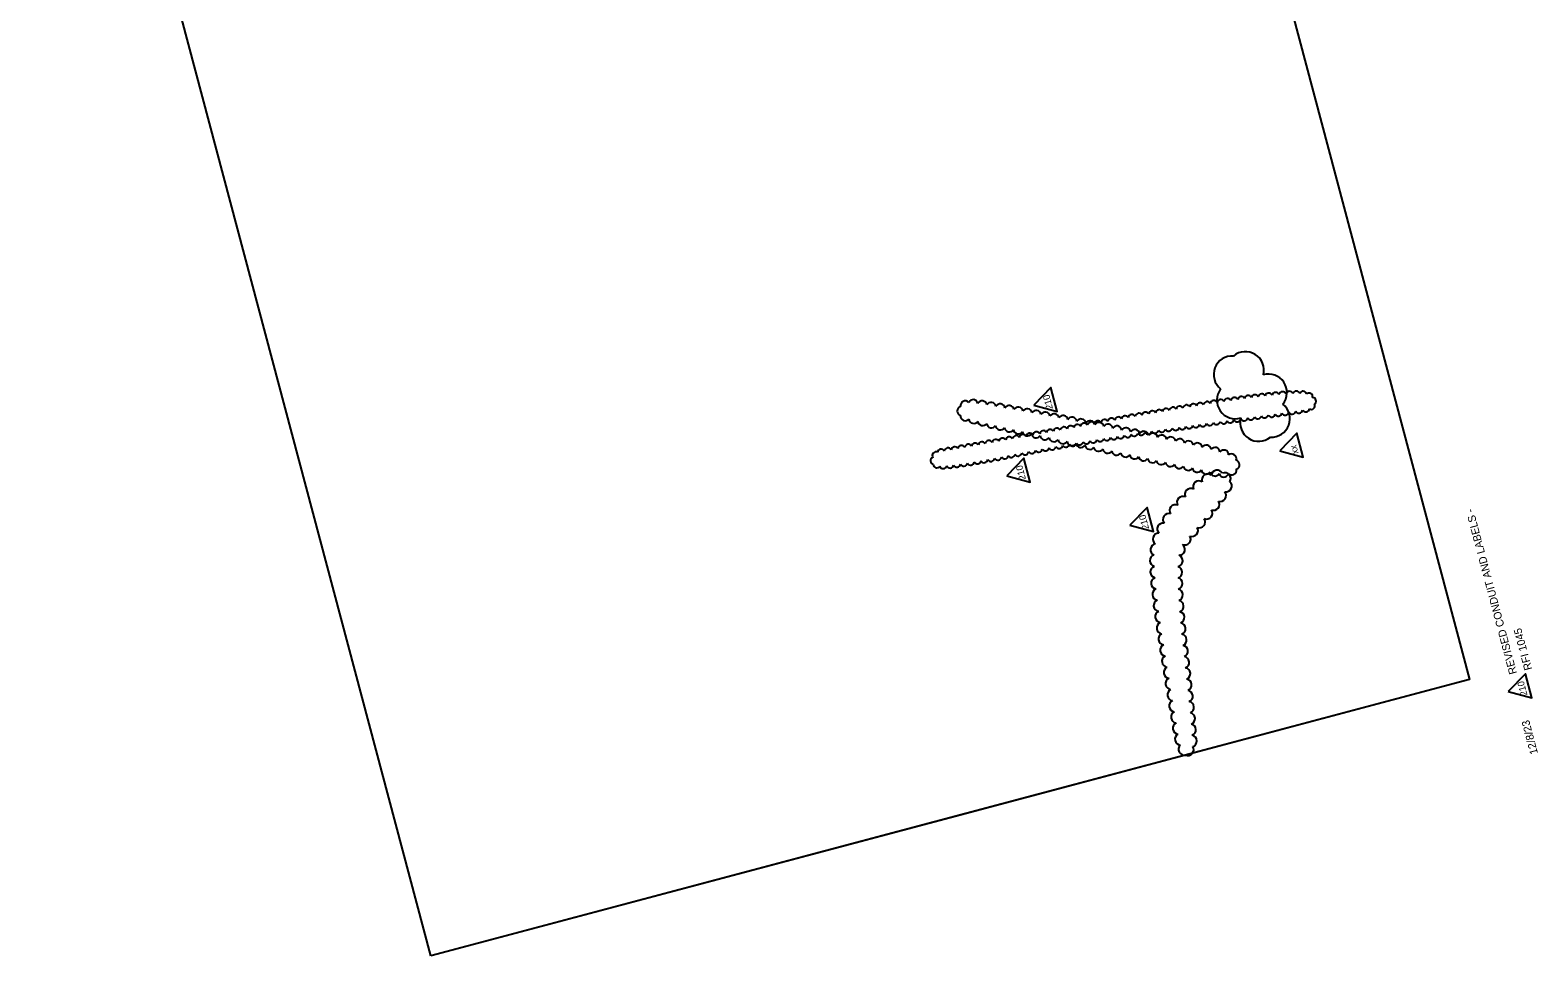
# Model space of a CAD drawing. Extents: x 930425 to 930963, y 629099 to 629760.
# Drawn here: x 930425 to 930963, y 629099 to 629430 of the extents above; entities that cross this region are included whole.
import ezdxf

# ---------------------------------------------------------------- set-up
doc = ezdxf.new("R2010")
doc.units = 0
for name, color, linetype in [('ActivePointCell_dp', 7, 'Continuous'), ('Cloud_dp', 7, 'Continuous'), ('MatchLines_dp', 7, 'Continuous'), ('TextMinor', 7, 'Continuous')]:
    doc.layers.add(name, color=color, linetype=linetype)

msp = doc.modelspace()

# ---------------------------------------------------------------- linework, layer by layer
at = {"layer": 'ActivePointCell_dp'}
msp.add_lwpolyline([(930567.78, 629098.98), (930424.61, 629637.39), (930795.69, 629736.06), (930938.85, 629197.65)], close=True, dxfattribs=at)
at = {"layer": 'Cloud_dp'}
for points in [[(930783.18, 629295.64), (930791.56, 629293.4), (930789.29, 629301.93)], [(930871.03, 629279.3), (930879.41, 629277.07), (930877.14, 629285.6)], [(930773.53, 629270.44), (930781.91, 629268.21), (930779.64, 629276.74)], [(930817.52, 629252.77), (930825.89, 629250.54), (930823.63, 629259.07)], [(930952.7, 629193.34), (930961.08, 629191.11), (930958.81, 629199.64)]]:
    msp.add_lwpolyline(points, close=True, dxfattribs=at)
for centre, radius, start, end in [((930854.07, 629306.59), 6.61, 86.2568, 231.2568), ((930858.79, 629308.17), 6.6, 345.4968, 130.4968), ((930867, 629300.17), 6.61, 321.0699, 106.0699), ((930855.17, 629297.42), 6.6, 142.5249, 287.5249), ((930758.69, 629295.46), 1.71, 43.9678, 188.9678), ((930761.48, 629295.93), 1.71, 10.359, 155.359), ((930764.7, 629295.48), 1.71, 8.6105, 153.6105), ((930767.92, 629294.96), 1.71, 7.9713, 152.9713), ((930771.14, 629294.41), 1.71, 7.609, 152.609), ((930840.18, 629294.83), 1.3, 26.844, 171.844), ((930842.62, 629295.23), 1.3, 26.7008, 171.7008), ((930845.07, 629295.62), 1.3, 26.5436, 171.5436), ((930847.51, 629296.01), 1.3, 26.37, 171.37), ((930849.95, 629296.38), 1.3, 26.177, 171.177), ((930852.4, 629296.75), 1.3, 25.9606, 170.9606), ((930854.85, 629297.11), 1.3, 25.7158, 170.7158), ((930857.3, 629297.46), 1.3, 25.4357, 170.4357), ((930859.74, 629297.79), 1.3, 25.1109, 170.1109), ((930862.2, 629298.11), 1.3, 24.7281, 169.7281), ((930864.65, 629298.41), 1.3, 24.2679, 169.2679), ((930867.1, 629298.69), 1.3, 23.7, 168.7), ((930868.07, 629290.83), 6.6, 266.857, 51.857), ((930869.56, 629298.94), 1.3, 22.9748, 167.9748), ((930872.02, 629299.16), 1.3, 22.0033, 167.0033), ((930874.48, 629299.32), 1.3, 20.605, 165.605), ((930876.94, 629299.41), 1.3, 18.3351, 163.3351), ((930879.38, 629299.34), 1.3, 13.5993, 158.5993), ((930881.5, 629298.68), 1.3, 346.9177, 131.9177), ((930882.27, 629295.45), 1.3, 240.1543, 25.1543), ((930882.73, 629297.09), 1.3, 303.2569, 88.2569), ((930757.5, 629293.55), 1.71, 106.9021, 251.9021), ((930758.68, 629291.82), 1.71, 176.383, 321.383), ((930761.73, 629290.83), 1.71, 182.8883, 327.8883), ((930774.36, 629293.84), 1.71, 7.3675, 152.3675), ((930777.57, 629293.26), 1.71, 7.1917, 152.1917), ((930780.79, 629292.67), 1.71, 7.0563, 152.0563), ((930784, 629292.08), 1.71, 6.9479, 151.9479), ((930787.21, 629291.48), 1.71, 6.8585, 151.8585), ((930790.42, 629290.87), 1.71, 6.7831, 151.7831), ((930793.63, 629290.26), 1.71, 6.7185, 151.7185), ((930796.84, 629289.65), 1.71, 6.6622, 151.6622), ((930800.05, 629289.03), 1.71, 6.6127, 151.6127), ((930808.51, 629289.25), 1.3, 27.8353, 172.8353), ((930810.94, 629289.7), 1.3, 27.8368, 172.8368), ((930813.38, 629290.14), 1.3, 27.8381, 172.8381), ((930815.81, 629290.59), 1.3, 27.8076, 172.8076), ((930818.24, 629291.03), 1.3, 27.737, 172.737), ((930820.68, 629291.46), 1.3, 27.6621, 172.6621), ((930823.11, 629291.9), 1.3, 27.5827, 172.5827), ((930825.55, 629292.33), 1.3, 27.4981, 172.4981), ((930827.99, 629292.76), 1.3, 27.4079, 172.4079), ((930830.43, 629293.18), 1.3, 27.3114, 172.3114), ((930832.86, 629293.6), 1.3, 27.2077, 172.2077), ((930835.3, 629294.02), 1.3, 27.096, 172.096), ((930837.74, 629294.43), 1.3, 26.9752, 171.9752), ((930855.85, 629290.99), 1.3, 205.3755, 350.3755), ((930863.52, 629289.34), 6.6, 164.3635, 309.3635), ((930858.3, 629291.33), 1.3, 205.399, 350.399), ((930860.75, 629291.67), 1.3, 205.4266, 350.4266), ((930863.2, 629292.01), 1.3, 205.4594, 350.4594), ((930865.65, 629292.36), 1.3, 205.4993, 350.4993), ((930868.1, 629292.7), 1.3, 205.5495, 350.5495), ((930870.55, 629293.05), 1.3, 205.6152, 350.6152), ((930873, 629293.4), 1.3, 205.7067, 350.7067), ((930875.45, 629293.76), 1.3, 205.847, 350.847), ((930877.9, 629294.12), 1.3, 206.1063, 351.1063), ((930880.34, 629294.51), 1.3, 206.992, 351.992), ((930764.89, 629290.04), 1.71, 183.793, 328.793), ((930768.06, 629289.28), 1.71, 184.2516, 329.2516), ((930771.24, 629288.54), 1.71, 184.5419, 329.5419), ((930774.43, 629287.81), 1.71, 184.747, 329.747), ((930777.62, 629287.09), 1.71, 184.9019, 329.9019), ((930779.29, 629283.93), 1.3, 27.8062, 172.8062), ((930780.81, 629286.38), 1.71, 185.0243, 330.0243), ((930781.73, 629284.38), 1.3, 27.8101, 172.8101), ((930784, 629285.68), 1.71, 185.1241, 330.1241), ((930784.16, 629284.82), 1.3, 27.8135, 172.8135), ((930786.59, 629285.26), 1.3, 27.8166, 172.8166), ((930789.03, 629285.7), 1.3, 27.8195, 172.8195), ((930791.46, 629286.15), 1.3, 27.822, 172.822), ((930793.9, 629286.59), 1.3, 27.8244, 172.8244), ((930796.33, 629287.04), 1.3, 27.8266, 172.8266), ((930798.77, 629287.48), 1.3, 27.8286, 172.8286), ((930801.2, 629287.92), 1.3, 27.8304, 172.8304), ((930803.26, 629288.41), 1.71, 6.5687, 151.5687), ((930803.64, 629288.37), 1.3, 27.8322, 172.8322), ((930806.07, 629288.81), 1.3, 27.8338, 172.8338), ((930806.47, 629287.79), 1.71, 6.5211, 151.5211), ((930809.68, 629287.17), 1.71, 6.4341, 151.4341), ((930812.88, 629286.54), 1.71, 6.3325, 151.3325), ((930816.09, 629285.9), 1.71, 6.2185, 151.2185), ((930816.64, 629285.44), 1.3, 206.1721, 351.1721), ((930819.29, 629285.26), 1.71, 6.0895, 151.0895), ((930819.09, 629285.82), 1.3, 206.0661, 351.0661), ((930821.54, 629286.18), 1.3, 205.9637, 350.9637), ((930822.49, 629284.61), 1.71, 5.942, 150.942), ((930823.99, 629286.54), 1.3, 205.8644, 350.8644), ((930825.69, 629283.95), 1.71, 5.771, 150.771), ((930826.44, 629286.9), 1.3, 205.7683, 350.7683), ((930828.88, 629287.26), 1.3, 205.6752, 350.6752), ((930831.34, 629287.61), 1.3, 205.5848, 350.5848), ((930833.79, 629287.95), 1.3, 205.4971, 350.4971), ((930836.24, 629288.29), 1.3, 205.4119, 350.4119), ((930838.69, 629288.63), 1.3, 205.3292, 350.3292), ((930841.14, 629288.97), 1.3, 205.283, 350.283), ((930843.59, 629289.31), 1.3, 205.294, 350.294), ((930846.05, 629289.64), 1.3, 205.3069, 350.3069), ((930848.5, 629289.98), 1.3, 205.3212, 350.3212), ((930850.95, 629290.31), 1.3, 205.3371, 350.3371), ((930853.4, 629290.65), 1.3, 205.3551, 350.3551), ((930750.07, 629278.65), 1.3, 27.7031, 172.7031), ((930752.5, 629279.09), 1.3, 27.5808, 172.5808), ((930754.94, 629279.52), 1.3, 27.6691, 172.6691), ((930757.37, 629279.96), 1.3, 27.7102, 172.7102), ((930759.81, 629280.4), 1.3, 27.7353, 172.7353), ((930762.25, 629280.84), 1.3, 27.7527, 172.7527), ((930764.68, 629281.28), 1.3, 27.7657, 172.7657), ((930767.12, 629281.72), 1.3, 27.7758, 172.7758), ((930769.55, 629282.16), 1.3, 27.7841, 172.7841), ((930771.99, 629282.61), 1.3, 27.7909, 172.7909), ((930774.42, 629283.05), 1.3, 27.7968, 172.7968), ((930776.86, 629283.49), 1.3, 27.8018, 172.8018), ((930784.9, 629280.13), 1.3, 207.9824, 352.9824), ((930787.19, 629284.98), 1.71, 185.2075, 330.2075), ((930787.34, 629280.58), 1.3, 207.8053, 352.8053), ((930789.77, 629281.02), 1.3, 207.6363, 352.6363), ((930790.38, 629284.29), 1.71, 185.2786, 330.2786), ((930792.21, 629281.45), 1.3, 207.4747, 352.4747), ((930793.58, 629283.6), 1.71, 185.3401, 330.3401), ((930794.65, 629281.88), 1.3, 207.3199, 352.3199), ((930796.77, 629282.91), 1.71, 185.394, 330.394), ((930797.09, 629282.3), 1.3, 207.1716, 352.1716), ((930799.97, 629282.23), 1.71, 185.4418, 330.4418), ((930799.53, 629282.71), 1.3, 207.0293, 352.0293), ((930801.97, 629283.12), 1.3, 206.8926, 351.8926), ((930803.16, 629281.55), 1.71, 185.4845, 330.4845), ((930804.42, 629283.52), 1.3, 206.7612, 351.7612), ((930806.36, 629280.87), 1.71, 185.5055, 330.5055), ((930806.86, 629283.91), 1.3, 206.6346, 351.6346), ((930809.56, 629280.19), 1.71, 185.5055, 330.5055), ((930809.3, 629284.3), 1.3, 206.5127, 351.5127), ((930811.75, 629284.69), 1.3, 206.3951, 351.3951), ((930814.19, 629285.07), 1.3, 206.2817, 351.2817), ((930828.89, 629283.28), 1.71, 5.5694, 150.5694), ((930832.09, 629282.6), 1.71, 5.327, 150.327), ((930835.28, 629281.9), 1.71, 5.0277, 150.0277), ((930838.46, 629281.18), 1.71, 4.6453, 149.6453), ((930841.64, 629280.44), 1.71, 4.1321, 149.1321), ((930844.81, 629279.67), 1.71, 3.3909, 148.3909), ((930847.96, 629278.84), 1.71, 2.1775, 147.1775), ((930747.55, 629275.81), 1.3, 111.2802, 256.2802), ((930748.21, 629277.65), 1.3, 64.1224, 209.1224), ((930748.54, 629274.56), 1.3, 180.3209, 325.3209), ((930755.71, 629274.79), 1.3, 205.3611, 350.3611), ((930758.15, 629275.15), 1.3, 206.2991, 351.2991), ((930760.59, 629275.54), 1.3, 206.9591, 351.9591), ((930763.03, 629275.96), 1.3, 207.4561, 352.4561), ((930765.46, 629276.4), 1.3, 207.8477, 352.8477), ((930767.89, 629276.85), 1.3, 208.1666, 353.1666), ((930770.32, 629277.31), 1.3, 208.4328, 353.4328), ((930772.75, 629277.78), 1.3, 208.6594, 353.6594), ((930775.17, 629278.27), 1.3, 208.763, 353.763), ((930777.6, 629278.75), 1.3, 208.5684, 353.5684), ((930780.03, 629279.22), 1.3, 208.3631, 353.3631), ((930782.47, 629279.68), 1.3, 208.1681, 353.1681), ((930812.75, 629279.51), 1.71, 185.5055, 330.5055), ((930815.95, 629278.83), 1.71, 185.5055, 330.5055), ((930819.15, 629278.15), 1.71, 185.5055, 330.5055), ((930822.35, 629277.47), 1.71, 185.5055, 330.5055), ((930825.54, 629276.79), 1.71, 185.5055, 330.5055), ((930828.74, 629276.11), 1.71, 185.5055, 330.5055), ((930831.94, 629275.43), 1.71, 185.5055, 330.5055), ((930835.13, 629274.75), 1.71, 185.5055, 330.5055), ((930851.07, 629277.91), 1.71, 359.5656, 144.5656), ((930853.83, 629276.54), 1.71, 342.5668, 127.5668), ((930854.98, 629274.38), 1.71, 288.8016, 73.8016), ((930750.82, 629274.28), 1.3, 200.9023, 345.9023), ((930753.26, 629274.49), 1.3, 203.8709, 348.8709), ((930838.33, 629274.07), 1.71, 185.5055, 330.5055), ((930841.53, 629273.39), 1.71, 185.5055, 330.5055), ((930844.73, 629272.71), 1.71, 185.5055, 330.5055), ((930845.31, 629268.95), 2.12, 52.5999, 197.5999), ((930847.92, 629272.04), 1.71, 185.5055, 330.5055), ((930848.69, 629270.35), 2.12, 27.379, 172.379), ((930851.05, 629271.69), 1.71, 197.0592, 342.0592), ((930851.44, 629269.4), 2.11, 329.2666, 114.2666), ((930853.86, 629272.41), 1.71, 226.7073, 11.7073), ((930839.25, 629263.8), 2.11, 61.5322, 206.5322), ((930842.19, 629266.51), 2.11, 58.6322, 203.6322), ((930849.79, 629263.42), 2.12, 252.2061, 37.2061), ((930851.8, 629266.79), 2.11, 261.3714, 46.3714), ((930833.78, 629257.98), 2.11, 67.8433, 212.8433), ((930836.42, 629260.96), 2.11, 63.8943, 208.8943), ((930844.88, 629257.08), 2.11, 248.2902, 33.2902), ((930847.4, 629260.22), 2.11, 249.2397, 34.2397), ((930829.34, 629251.42), 2.11, 79.8829, 224.8829), ((930831.38, 629254.81), 2.11, 73.0241, 218.0241), ((930842.32, 629253.96), 2.11, 247.9061, 32.9061), ((930827.81, 629247.82), 2.11, 89.0457, 234.0457), ((930837.12, 629247.82), 2.11, 246.4392, 31.4392), ((930839.74, 629250.87), 2.11, 247.3238, 32.3238), ((930826.74, 629240.09), 2.11, 108.1173, 253.1173), ((930826.96, 629244.03), 2.11, 100.5875, 245.5875), ((930834.29, 629240.07), 2.11, 282.9345, 67.9345), ((930835.07, 629244.14), 2.11, 270.3024, 55.3024), ((930826.89, 629236.09), 2.11, 111.141, 256.141), ((930834.11, 629235.99), 2.11, 287.0081, 72.0081), ((930827.2, 629232.09), 2.11, 112.8285, 257.8285), ((930834.15, 629231.94), 2.11, 289.2077, 74.2077), ((930827.62, 629228.09), 2.11, 113.942, 258.942), ((930828.09, 629224.1), 2.11, 114.747, 259.747), ((930834.32, 629227.89), 2.11, 290.6341, 75.6341), ((930834.58, 629223.85), 2.11, 291.6542, 76.6542), ((930828.62, 629220.1), 2.11, 115.3638, 260.3638), ((930834.9, 629219.82), 2.11, 292.4299, 77.4299), ((930829.19, 629216.12), 2.11, 115.8559, 260.8559), ((930835.27, 629215.8), 2.11, 293.0453, 78.0453), ((930829.79, 629212.13), 2.11, 116.2602, 261.2602), ((930830.42, 629208.15), 2.11, 116.6001, 261.6001), ((930835.68, 629211.78), 2.11, 293.5488, 78.5488), ((930836.12, 629207.77), 2.11, 293.9558, 78.9558), ((930831.06, 629204.17), 2.11, 116.7742, 261.7742), ((930836.57, 629203.76), 2.11, 293.9754, 78.9754), ((930831.71, 629200.19), 2.11, 116.7751, 261.7751), ((930837.02, 629199.75), 2.11, 293.8288, 78.8288), ((930832.36, 629196.21), 2.11, 116.7751, 261.7751), ((930833.01, 629192.23), 2.11, 116.7751, 261.7751), ((930837.46, 629195.74), 2.11, 293.6486, 78.6486), ((930837.88, 629191.73), 2.11, 293.4194, 78.4194), ((930833.66, 629188.24), 2.11, 116.7751, 261.7751), ((930838.29, 629187.72), 2.11, 293.114, 78.114), ((930834.31, 629184.26), 2.11, 116.7751, 261.7751), ((930838.67, 629183.71), 2.11, 292.6778, 77.6778), ((930834.96, 629180.28), 2.11, 116.7751, 261.7751), ((930835.71, 629176.35), 2.11, 119.6448, 264.6448), ((930839.01, 629179.7), 2.11, 291.9773, 76.9773), ((930839.27, 629175.69), 2.12, 290.5397, 75.5397), ((930837, 629172.75), 2.11, 134.9721, 279.9721), ((930838.21, 629172.61), 2.11, 246.5523, 31.5523)]:
    msp.add_arc(centre, radius, start, end, dxfattribs=at)
at = {"layer": 'MatchLines_dp'}
msp.add_lwpolyline([(930938.85, 629197.65), (930753.31, 629148.32), (930567.78, 629098.98)], dxfattribs=at)

# ---------------------------------------------------------------- texts
at = {"layer": 'Cloud_dp'}
for s, p in [('210', (930790.04, 629294.43)), ('xx', (930877.77, 629278.52)), ('210', (930780.39, 629269.23)), ('210', (930824.38, 629251.56)), ('210', (930959.56, 629192.14))]:
    msp.add_text(s, height=2.399, rotation=104.8905, dxfattribs=at).set_placement(p)
at = {"layer": 'TextMinor'}
for s, p in [('REVISED CONDUIT AND LABELS - ', (930955.82, 629199.93)), ('RFI 1045', (930961.23, 629201.37)), ('12/8/23', (930963.32, 629171.33))]:
    msp.add_text(s, height=2.8, rotation=104.8905, dxfattribs=at).set_placement(p)

doc.saveas('drawing.dxf')
